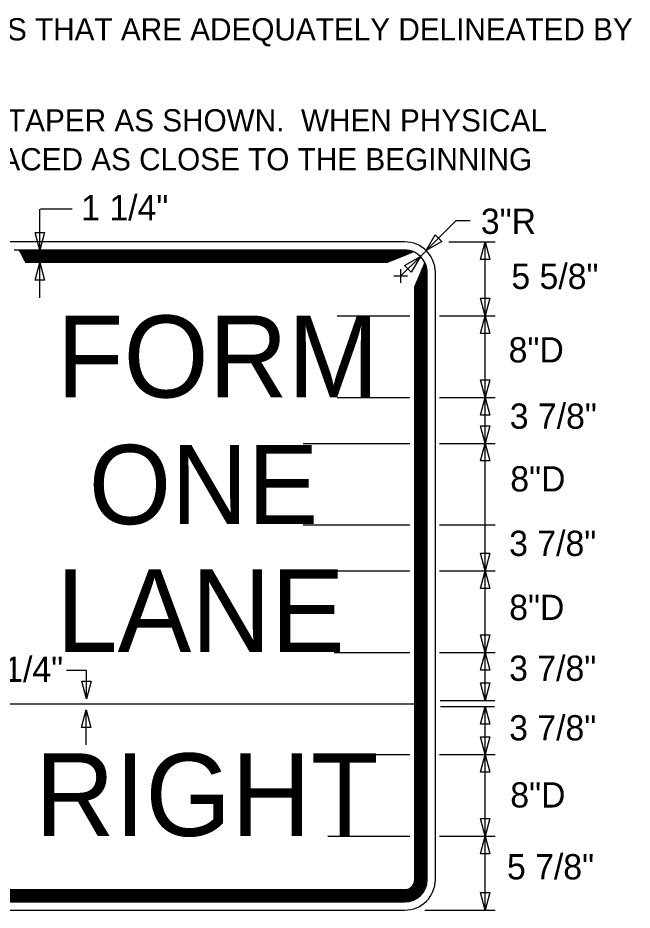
# Model space of a CAD drawing. Extents: x 15262 to 18126, y 1908 to 6555.
# Drawn here: x 17847.7 to 18052, y 2366.5 to 2663.3 of the extents above; entities that cross this region are included whole.
import ezdxf

# ---------------------------------------------------------------- set-up
doc = ezdxf.new("R2010")
doc.units = 0
for name, color, linetype in [('TYPICAL_EX', 7, 'Continuous'), ('TYPICAL_TEXT_DIMEN_EX', 7, 'Continuous'), ('TYPICAL_TEXT_DIMEN_PR', 7, 'Continuous')]:
    doc.layers.add(name, color=color, linetype=linetype)

msp = doc.modelspace()

# ---------------------------------------------------------------- linework, layer by layer
at = {"layer": 'TYPICAL_EX'}
for p, q in [((17976.4, 2588.82), (17833.88, 2588.82)), ((17976.4, 2586.1), (17846.51, 2586.1)), ((17976.4, 2585.99), (17848.04, 2585.99)), ((17976.4, 2585.88), (17848.18, 2585.88)), ((17976.4, 2585.77), (17848.24, 2585.77)), ((17976.4, 2585.66), (17848.29, 2585.66)), ((17976.4, 2585.54), (17848.35, 2585.54)), ((17976.4, 2585.43), (17848.41, 2585.43)), ((17976.4, 2585.32), (17848.47, 2585.32)), ((17976.4, 2585.21), (17848.53, 2585.21)), ((17976.4, 2585.1), (17848.58, 2585.1)), ((17976.4, 2584.98), (17848.64, 2584.98)), ((17976.4, 2584.87), (17848.7, 2584.87)), ((17976.4, 2584.76), (17848.76, 2584.76)), ((17976.4, 2584.65), (17848.82, 2584.65)), ((17976.4, 2584.53), (17848.87, 2584.53)), ((17976.4, 2584.42), (17848.93, 2584.42)), ((17976.4, 2584.31), (17848.99, 2584.31)), ((17976.26, 2584.2), (17849.05, 2584.2)), ((17975.99, 2584.09), (17849.1, 2584.09)), ((17975.7, 2583.97), (17849.16, 2583.97)), ((17975.42, 2583.86), (17849.22, 2583.86)), ((17975.14, 2583.75), (17849.28, 2583.75)), ((17974.86, 2583.64), (17849.34, 2583.64)), ((17974.58, 2583.53), (17849.4, 2583.53)), ((17974.3, 2583.41), (17849.45, 2583.41)), ((17974.02, 2583.3), (17849.51, 2583.3)), ((17973.74, 2583.19), (17849.57, 2583.19)), ((17973.46, 2583.08), (17849.63, 2583.08)), ((17973.18, 2582.97), (17849.69, 2582.97)), ((17972.9, 2582.85), (17849.74, 2582.85)), ((17972.62, 2582.74), (17849.8, 2582.74)), ((17972.34, 2582.63), (17849.86, 2582.63)), ((17972.06, 2582.52), (17849.92, 2582.52)), ((17971.78, 2582.41), (17849.97, 2582.41)), ((17971.49, 2582.29), (17850.03, 2582.29)), ((17971.21, 2582.18), (17850.09, 2582.18)), ((17970.93, 2582.07), (17850.15, 2582.07)), ((17970.75, 2581.99), (17850.19, 2581.99)), ((17980.84, 2430.48), (17980.84, 2576.57)), ((17980.95, 2430.5), (17980.95, 2576.83)), ((17981.06, 2430.55), (17981.06, 2577.09)), ((17981.17, 2430.59), (17981.17, 2577.35)), ((17981.28, 2430.53), (17981.28, 2577.61)), ((17981.4, 2430.55), (17981.4, 2577.87)), ((17981.51, 2430.53), (17981.51, 2578.13)), ((17981.62, 2430.42), (17981.62, 2578.39)), ((17981.73, 2430.57), (17981.73, 2578.64)), ((17981.84, 2430.59), (17981.84, 2578.64)), ((17981.96, 2430.57), (17981.96, 2578.64)), ((17982.07, 2430.46), (17982.07, 2578.64)), ((17982.18, 2430.53), (17982.18, 2578.64)), ((17982.29, 2430.59), (17982.29, 2578.64)), ((17982.4, 2430.63), (17982.4, 2578.64)), ((17982.52, 2430.55), (17982.52, 2578.64)), ((17982.63, 2430.59), (17982.63, 2578.64)), ((17982.74, 2430.55), (17982.74, 2578.64)), ((17982.85, 2430.57), (17982.85, 2578.64)), ((17982.97, 2430.57), (17982.97, 2578.64)), ((17983.08, 2430.57), (17983.08, 2578.64)), ((17983.19, 2430.61), (17983.19, 2578.64)), ((17983.3, 2430.63), (17983.3, 2578.64)), ((17983.41, 2430.57), (17983.41, 2578.64)), ((17983.53, 2430.57), (17983.53, 2578.64)), ((17983.64, 2430.61), (17983.64, 2578.64)), ((17983.75, 2430.57), (17983.75, 2578.64)), ((17983.86, 2430.62), (17983.86, 2578.64)), ((17986.58, 2430.6), (17986.58, 2578.64)), ((17979.75, 2430.55), (17979.75, 2574.06)), ((17979.83, 2430.55), (17979.83, 2574.23)), ((17979.94, 2430.65), (17979.94, 2574.49)), ((17980.05, 2430.63), (17980.05, 2574.75)), ((17980.16, 2430.55), (17980.16, 2575.01)), ((17980.28, 2430.55), (17980.28, 2575.27)), ((17980.39, 2430.63), (17980.39, 2575.53)), ((17980.5, 2430.48), (17980.5, 2575.79)), ((17980.61, 2430.57), (17980.61, 2576.05)), ((17980.73, 2430.59), (17980.73, 2576.31)), ((17830.94, 2435.12), (17979.69, 2435.12)), ((17979.75, 2376.7), (17979.75, 2430.55)), ((17979.83, 2376.7), (17979.83, 2430.55)), ((17979.94, 2376.7), (17979.94, 2430.55)), ((17980.05, 2376.7), (17980.05, 2430.55)), ((17980.16, 2376.7), (17980.16, 2430.55)), ((17980.28, 2376.7), (17980.28, 2430.55)), ((17980.39, 2376.7), (17980.39, 2430.55)), ((17980.5, 2376.7), (17980.5, 2430.55)), ((17980.61, 2376.7), (17980.61, 2430.55)), ((17980.72, 2376.7), (17980.72, 2430.55)), ((17980.84, 2376.7), (17980.84, 2430.55)), ((17980.95, 2376.7), (17980.95, 2430.55)), ((17981.06, 2376.7), (17981.06, 2430.55)), ((17981.17, 2376.7), (17981.17, 2430.55)), ((17981.28, 2376.7), (17981.28, 2430.55)), ((17981.4, 2376.7), (17981.4, 2430.55)), ((17981.51, 2376.7), (17981.51, 2430.55)), ((17981.62, 2376.7), (17981.62, 2430.55)), ((17981.73, 2376.7), (17981.73, 2430.55)), ((17981.84, 2376.7), (17981.84, 2430.55)), ((17981.96, 2376.7), (17981.96, 2430.55)), ((17982.07, 2376.7), (17982.07, 2430.55)), ((17982.18, 2376.7), (17982.18, 2430.55)), ((17982.29, 2376.7), (17982.29, 2430.55)), ((17982.4, 2376.7), (17982.4, 2430.55)), ((17982.52, 2376.7), (17982.52, 2430.55)), ((17982.63, 2376.7), (17982.63, 2430.55)), ((17982.74, 2376.7), (17982.74, 2430.55)), ((17982.85, 2376.7), (17982.85, 2430.55)), ((17982.97, 2376.7), (17982.97, 2430.55)), ((17983.08, 2376.7), (17983.08, 2430.55)), ((17983.19, 2376.7), (17983.19, 2430.55)), ((17983.3, 2376.7), (17983.3, 2430.55)), ((17983.41, 2376.7), (17983.41, 2430.55)), ((17983.53, 2376.7), (17983.53, 2430.55)), ((17983.64, 2376.7), (17983.64, 2430.55)), ((17983.75, 2376.7), (17983.75, 2430.55)), ((17983.86, 2376.7), (17983.86, 2430.55)), ((17986.58, 2376.7), (17986.58, 2430.55)), ((17833.88, 2373.35), (17976.4, 2373.35)), ((17833.88, 2373.27), (17976.4, 2373.27)), ((17833.88, 2373.16), (17976.4, 2373.16)), ((17833.88, 2373.05), (17976.4, 2373.05)), ((17833.88, 2372.94), (17976.4, 2372.94)), ((17833.88, 2372.83), (17976.4, 2372.83)), ((17833.88, 2372.71), (17976.4, 2372.71)), ((17833.88, 2372.6), (17976.4, 2372.6)), ((17833.88, 2372.49), (17976.4, 2372.49)), ((17833.88, 2372.38), (17976.4, 2372.38)), ((17833.88, 2372.27), (17976.4, 2372.27)), ((17833.88, 2372.15), (17976.4, 2372.15)), ((17833.88, 2372.04), (17976.4, 2372.04)), ((17833.88, 2371.93), (17976.4, 2371.93)), ((17833.88, 2371.82), (17976.4, 2371.82)), ((17833.88, 2371.7), (17976.4, 2371.7)), ((17833.88, 2371.59), (17976.4, 2371.59)), ((17833.88, 2371.48), (17976.4, 2371.48)), ((17833.88, 2371.37), (17976.4, 2371.37)), ((17833.88, 2371.26), (17976.4, 2371.26)), ((17833.88, 2371.14), (17976.4, 2371.14)), ((17833.88, 2371.03), (17976.4, 2371.03)), ((17833.88, 2370.92), (17976.4, 2370.92)), ((17833.88, 2370.81), (17976.4, 2370.81)), ((17833.88, 2370.7), (17976.4, 2370.7)), ((17833.88, 2370.59), (17976.4, 2370.59)), ((17833.88, 2370.47), (17976.4, 2370.47)), ((17833.88, 2370.36), (17976.4, 2370.36)), ((17833.88, 2370.25), (17976.4, 2370.25)), ((17833.88, 2370.14), (17976.4, 2370.14)), ((17833.88, 2370.02), (17976.4, 2370.02)), ((17833.88, 2369.91), (17976.4, 2369.91)), ((17833.88, 2369.8), (17976.4, 2369.8)), ((17833.88, 2369.69), (17976.4, 2369.69)), ((17833.88, 2369.58), (17976.4, 2369.58)), ((17833.88, 2369.46), (17976.4, 2369.46)), ((17833.88, 2369.35), (17976.4, 2369.35)), ((17833.88, 2369.24), (17976.4, 2369.24)), ((17833.88, 2366.53), (17976.4, 2366.53))]:
    msp.add_line(p, q, dxfattribs=at)
for centre, radius, start, end in [((17976.4, 2578.64), 10.18, 0, 90), ((17976.4, 2578.64), 7.46, 39.0673, 90), ((17976.4, 2578.64), 7.35, 66.9087, 90), ((17976.4, 2578.64), 7.24, 67.8069, 90), ((17976.4, 2578.64), 7.13, 68.7489, 90), ((17976.4, 2578.64), 7.02, 69.7388, 90), ((17976.4, 2578.64), 6.9, 70.7811, 90), ((17976.4, 2578.64), 6.79, 71.8812, 90), ((17976.4, 2578.64), 6.68, 73.0455, 90), ((17976.4, 2578.64), 6.57, 74.2814, 90), ((17976.4, 2578.64), 6.46, 75.5979, 90), ((17976.4, 2578.64), 6.34, 77.006, 90), ((17976.4, 2578.64), 6.23, 78.5194, 90), ((17976.4, 2578.64), 6.12, 80.1555, 90), ((17976.4, 2578.64), 6.01, 81.9371, 90), ((17976.4, 2578.64), 5.9, 83.8949, 90), ((17976.4, 2578.64), 5.78, 86.0727, 90), ((17976.4, 2578.64), 5.67, 88.5362, 90), ((17976.4, 2578.64), 7.46, 0, 39.0664), ((17976.4, 2578.64), 5.78, 0, 8.847), ((17976.4, 2578.64), 5.9, 0, 10.5386), ((17976.4, 2578.64), 6.01, 0, 12.0996), ((17976.4, 2578.64), 6.12, 0, 13.5489), ((17976.4, 2578.64), 6.23, 0, 14.9011), ((17976.4, 2578.64), 6.34, 0, 16.1683), ((17976.4, 2578.64), 6.46, 0, 17.36), ((17976.4, 2578.64), 6.57, 0, 18.4842), ((17976.4, 2578.64), 6.68, 0, 19.5478), ((17976.4, 2578.64), 6.79, 0, 20.5564), ((17976.4, 2578.64), 6.9, 0, 21.5151), ((17976.4, 2578.64), 7.02, 0, 22.4279), ((17976.4, 2578.64), 7.13, 0, 23.2988), ((17976.4, 2578.64), 7.24, 0, 24.1309), ((17976.4, 2578.64), 7.35, 0, 24.1308), ((17976.4, 2578.64), 5.34, 0, 0.1031), ((17976.4, 2578.64), 5.45, 0, 2.6891), ((17976.4, 2578.64), 5.56, 0, 4.9634), ((17976.4, 2578.64), 5.67, 0, 6.9999), ((17976.4, 2376.71), 7.46, 270, 0), ((17976.4, 2376.71), 3.36, 270, 0), ((17976.4, 2376.71), 7.35, 270, 0), ((17976.4, 2376.71), 7.24, 270, 0), ((17976.4, 2376.71), 7.13, 270, 0), ((17976.4, 2376.71), 7.02, 270, 0), ((17976.4, 2376.71), 6.9, 270, 0), ((17976.4, 2376.71), 6.79, 270, 0), ((17976.4, 2376.71), 6.68, 270, 0), ((17976.4, 2376.71), 6.57, 270, 0), ((17976.4, 2376.71), 6.46, 270, 0), ((17976.4, 2376.71), 6.34, 270, 0), ((17976.4, 2376.71), 6.23, 270, 0), ((17976.4, 2376.71), 6.12, 270, 0), ((17976.4, 2376.71), 6.01, 270, 0), ((17976.4, 2376.71), 5.9, 270, 0), ((17976.4, 2376.71), 5.78, 270, 0), ((17976.4, 2376.71), 5.67, 270, 0), ((17976.4, 2376.71), 5.56, 270, 0), ((17976.4, 2376.71), 5.45, 270, 0), ((17976.4, 2376.71), 5.34, 270, 0), ((17976.4, 2376.71), 5.22, 270, 0), ((17976.4, 2376.71), 5.11, 270, 0), ((17976.4, 2376.71), 5, 270, 0), ((17976.4, 2376.71), 4.89, 270, 0), ((17976.4, 2376.71), 4.78, 270, 0), ((17976.4, 2376.71), 4.66, 270, 0), ((17976.4, 2376.71), 4.55, 270, 0), ((17976.4, 2376.71), 4.44, 270, 0), ((17976.4, 2376.71), 4.33, 270, 0), ((17976.4, 2376.71), 4.21, 270, 0), ((17976.4, 2376.71), 4.1, 270, 0), ((17976.4, 2376.71), 3.99, 270, 0), ((17976.4, 2376.71), 3.88, 270, 0), ((17976.4, 2376.71), 3.77, 270, 0), ((17976.4, 2376.71), 3.65, 270, 0), ((17976.4, 2376.71), 3.54, 270, 0), ((17976.4, 2376.71), 3.43, 270, 0), ((17976.4, 2376.71), 10.18, 270, 0)]:
    msp.add_arc(centre, radius, start, end, dxfattribs=at)
at = {"layer": 'TYPICAL_TEXT_DIMEN_PR'}
for p, q in [((17855.03, 2586.1), (17855.03, 2599.74)), ((17855.2, 2599.81), (17865.77, 2599.81)), ((17983.51, 2585.92), (17993.46, 2595.88)), ((17993.46, 2595.88), (17998.17, 2595.88)), ((17855.03, 2586.1), (17853.46, 2591.97)), ((17853.46, 2591.97), (17855.03, 2591.97)), ((17855.03, 2591.97), (17856.6, 2591.97)), ((17856.6, 2591.97), (17855.03, 2586.1)), ((17983.51, 2585.92), (17986.54, 2591.18)), ((17988.76, 2588.96), (17983.51, 2585.92)), ((17986.54, 2591.18), (17987.65, 2590.07)), ((17987.65, 2590.07), (17988.76, 2588.96)), ((17991.1, 2588.82), (18006.46, 2588.82)), ((18001.57, 2582.96), (18003.14, 2588.82)), ((18003.14, 2564.22), (18003.14, 2588.82)), ((18003.14, 2588.82), (18004.71, 2582.96)), ((17855.03, 2586.36), (17855.03, 2586.37)), ((17855.03, 2586.36), (17855.03, 2586.36)), ((17981.59, 2584.01), (17983.48, 2585.89)), ((17975.06, 2577.48), (17981.59, 2584.01)), ((17976.33, 2580.97), (17981.59, 2584)), ((17981.59, 2584), (17978.55, 2578.75)), ((18003.14, 2582.96), (18001.57, 2582.96)), ((18004.71, 2582.96), (18003.14, 2582.96)), ((17853.46, 2576.13), (17855.03, 2581.99)), ((17855.03, 2570.22), (17855.03, 2581.99)), ((17855.03, 2581.99), (17856.6, 2576.13)), ((17975.06, 2575.24), (17975.06, 2579.72)), ((17977.44, 2579.86), (17976.33, 2580.97)), ((17978.55, 2578.75), (17977.44, 2579.86)), ((17972.82, 2577.48), (17975.06, 2577.48)), ((17975.06, 2577.48), (17977.3, 2577.48)), ((17855.03, 2576.13), (17853.46, 2576.13)), ((17856.6, 2576.13), (17855.03, 2576.13)), ((18003.14, 2564.22), (18001.57, 2570.08)), ((18001.57, 2570.08), (18003.14, 2570.08)), ((18003.14, 2570.08), (18004.71, 2570.08)), ((18004.71, 2570.08), (18003.14, 2564.22)), ((17953.92, 2564.22), (17978.09, 2564.22)), ((17987.94, 2564.22), (18006.46, 2564.22)), ((18001.57, 2558.36), (18003.14, 2564.22)), ((18003.14, 2537.07), (18003.14, 2564.22)), ((18003.14, 2564.22), (18004.71, 2558.36)), ((18003.14, 2558.36), (18001.57, 2558.36)), ((18004.71, 2558.36), (18003.14, 2558.36)), ((18003.14, 2537.07), (18001.57, 2542.94)), ((18001.57, 2542.94), (18003.14, 2542.94)), ((18003.14, 2542.94), (18004.71, 2542.94)), ((18004.71, 2542.94), (18003.14, 2537.07)), ((17953.92, 2537.07), (17978.09, 2537.07)), ((17987.94, 2537.07), (18006.46, 2537.07)), ((18001.57, 2531.21), (18003.14, 2537.07)), ((18003.14, 2521.8), (18003.14, 2537.07)), ((18003.14, 2537.07), (18004.71, 2531.21)), ((18003.14, 2531.21), (18001.57, 2531.21)), ((18004.71, 2531.21), (18003.14, 2531.21)), ((18003.14, 2521.8), (18001.57, 2527.67)), ((18001.57, 2527.67), (18003.14, 2527.67)), ((18003.14, 2527.67), (18004.71, 2527.67)), ((18004.71, 2527.67), (18003.14, 2521.8)), ((17942.66, 2521.8), (17978.09, 2521.8)), ((17987.94, 2521.8), (18006.46, 2521.8)), ((18001.57, 2515.94), (18003.14, 2521.8)), ((18003.14, 2494.66), (18003.14, 2521.8)), ((18003.14, 2521.8), (18004.71, 2515.94)), ((18003.14, 2515.94), (18001.57, 2515.94)), ((18004.71, 2515.94), (18003.14, 2515.94)), ((17942.66, 2494.66), (17978.09, 2494.66)), ((17987.94, 2494.66), (18006.46, 2494.66)), ((18003.14, 2479.39), (18003.14, 2494.66)), ((18003.14, 2479.39), (18001.57, 2485.25)), ((18001.57, 2485.25), (18003.14, 2485.25)), ((18003.14, 2485.25), (18004.71, 2485.25)), ((18004.71, 2485.25), (18003.14, 2479.39)), ((17952.91, 2479.39), (17978.09, 2479.39)), ((17987.94, 2479.39), (18006.46, 2479.39)), ((18001.57, 2473.53), (18003.14, 2479.39)), ((18003.14, 2452.24), (18003.14, 2479.39)), ((18003.14, 2479.39), (18004.71, 2473.53)), ((18003.14, 2473.53), (18001.57, 2473.53)), ((18004.71, 2473.53), (18003.14, 2473.53)), ((18003.14, 2452.24), (18001.57, 2458.11)), ((18001.57, 2458.11), (18003.14, 2458.11)), ((18003.14, 2458.11), (18004.71, 2458.11)), ((18004.71, 2458.11), (18003.14, 2452.24)), ((17952.91, 2452.24), (17978.09, 2452.24)), ((17987.94, 2452.24), (18006.46, 2452.24)), ((18001.57, 2446.38), (18003.14, 2452.24)), ((18003.14, 2436.27), (18003.14, 2452.24)), ((18003.14, 2452.24), (18003.14, 2452.24)), ((18003.14, 2452.24), (18003.14, 2452.24)), ((18003.14, 2452.24), (18004.71, 2446.38)), ((17870.56, 2446.28), (17863.9, 2446.28)), ((17870.56, 2436.83), (17870.56, 2446.28)), ((18003.14, 2446.38), (18001.57, 2446.38)), ((18004.71, 2446.38), (18003.14, 2446.38)), ((17870.56, 2436.83), (17868.99, 2442.69)), ((17868.99, 2442.69), (17870.56, 2442.69)), ((17870.56, 2442.69), (17872.13, 2442.69)), ((17872.13, 2442.69), (17870.56, 2436.83)), ((18003.14, 2436.27), (18001.57, 2442.13)), ((18001.57, 2442.13), (18003.14, 2442.13)), ((18003.14, 2442.13), (18004.71, 2442.13)), ((18004.71, 2442.13), (18003.14, 2436.27)), ((17988.19, 2436.27), (18006.38, 2436.27)), ((17988.29, 2434.26), (18006.28, 2434.26)), ((18001.57, 2428.39), (18003.14, 2434.25)), ((18003.14, 2418.27), (18003.14, 2434.25)), ((18003.14, 2434.25), (18004.71, 2428.39)), ((17868.82, 2427.3), (17870.39, 2433.16)), ((17870.39, 2421.51), (17870.39, 2433.16)), ((17870.39, 2433.16), (17871.96, 2427.3)), ((18003.14, 2428.39), (18001.57, 2428.39)), ((18004.71, 2428.39), (18003.14, 2428.39)), ((18004.36, 2430.55), (18004.36, 2430.54)), ((17870.39, 2427.3), (17868.82, 2427.3)), ((17871.96, 2427.3), (17870.39, 2427.3)), ((18003.14, 2418.27), (18001.57, 2424.13)), ((18001.57, 2424.13), (18003.14, 2424.13)), ((18003.14, 2424.13), (18004.71, 2424.13)), ((18004.71, 2424.13), (18003.14, 2418.27)), ((17958.23, 2418.27), (17978.09, 2418.27)), ((17987.94, 2418.27), (18006.46, 2418.27)), ((18001.57, 2412.41), (18003.14, 2418.27)), ((18003.14, 2391.12), (18003.14, 2418.27)), ((18003.14, 2418.27), (18004.71, 2412.41)), ((18003.14, 2412.41), (18001.57, 2412.41)), ((18004.71, 2412.41), (18003.14, 2412.41)), ((18003.14, 2391.12), (18001.57, 2396.99)), ((18001.57, 2396.99), (18003.14, 2396.99)), ((18003.14, 2396.99), (18004.71, 2396.99)), ((18004.71, 2396.99), (18003.14, 2391.12)), ((17950.81, 2391.12), (17978.09, 2391.12)), ((17987.94, 2391.12), (18006.46, 2391.12)), ((18001.57, 2385.26), (18003.14, 2391.12)), ((18003.14, 2366.53), (18003.14, 2391.12)), ((18003.14, 2391.12), (18004.71, 2385.26)), ((18003.14, 2385.26), (18001.57, 2385.26)), ((18004.71, 2385.26), (18003.14, 2385.26)), ((18003.14, 2366.53), (18001.57, 2372.39)), ((18001.57, 2372.39), (18003.14, 2372.39)), ((18003.14, 2372.39), (18004.71, 2372.39)), ((18004.71, 2372.39), (18003.14, 2366.53)), ((17983.09, 2366.53), (18006.46, 2366.53))]:
    msp.add_line(p, q, dxfattribs=at)

# ---------------------------------------------------------------- texts
at = {"layer": 'TYPICAL_TEXT_DIMEN_EX'}
for s, height, p in [('FORM', 27.241, (17860.6, 2537.08)), ('ONE', 26.355, (17871.29, 2494.93)), ('LANE', 27.463, (17860.46, 2452.42)), ('RIGHT', 27.463, (17853.39, 2391.2))]:
    msp.add_text(s, height=height, dxfattribs=at).set_placement(p)
at = {"layer": 'TYPICAL_TEXT_DIMEN_PR'}
for s, height, p in [('PATTERN.  EXCEPTION WILL BE MADE FOR DAYTIME-ONLY TRAFFIC PATTERNS THAT ARE ADEQUATELY DELINEATED BY', 7.392, (17465.67, 2655.84)), ('THE LIGHTED ARROW PANEL SHALL BE LOCATED AT THE BEGINNING OF THE TAPER AS SHOWN.  WHEN PHYSICAL', 7.392, (17465.67, 2625.55)), ('LIMITATIONS RESTRICT ITS PLACEMENT AS INDICATED, THEN IT SHALL BE PLACED AS CLOSE TO THE BEGINNING', 7.392, (17465.67, 2612.61)), ('1 1/4"', 8.4, (17868.78, 2596)), ('3"R', 8.4, (18001.72, 2591.48)), ('5 5/8"', 8.4, (18011.87, 2573.16)), ('8"D', 8.4, (18010.96, 2548.72)), ('3 7/8"', 8.4, (18011.33, 2526.66)), ('8"D', 8.4, (18011.51, 2505.8)), ('3 7/8"', 8.4, (18011.14, 2484.35)), ('8"D', 8.4, (18011.15, 2463.06)), ('1 1/4"', 8.4, (17833.8, 2442.45)), ('3 7/8"', 8.4, (18011.14, 2442.8)), ('3 7/8"', 8.4, (18011.14, 2422.98)), ('8"D', 8.4, (18011.51, 2400.67)), ('5 7/8"', 8.4, (18010.4, 2376.76))]:
    msp.add_text(s, height=height, dxfattribs=at).set_placement(p)

doc.saveas('drawing.dxf')
